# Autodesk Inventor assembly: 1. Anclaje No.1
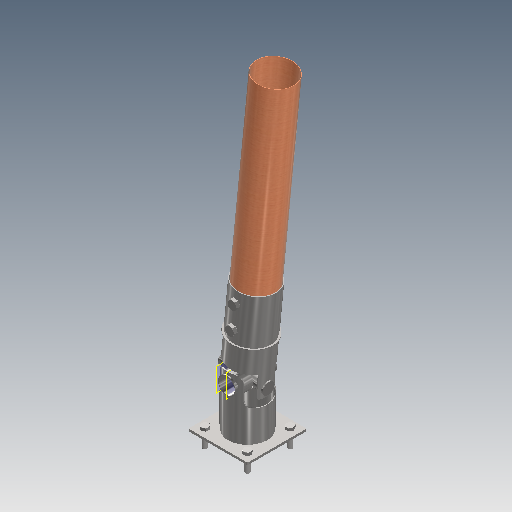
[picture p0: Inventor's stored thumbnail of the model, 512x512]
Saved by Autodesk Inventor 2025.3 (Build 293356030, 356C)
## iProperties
Created: 2025-10
Part Number: 1. Anclaje No.1
Document SubType Name: Assembly
Designer: Asus
Author: Asus
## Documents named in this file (10)
- C:\Users\User\OneDrive - Institucion Universitaria Colegio Mayor de Antioquia\Escritorio\PROTECTO INV\Anclajes Profesor\1. Anclaje de Platinas\1. Anclaje No.1.iam
- C:\Users\User\OneDrive - Institucion Universitaria Colegio Mayor de Antioquia\Escritorio\PROTECTO INV\Anclajes Profesor\1. Anclaje de Platinas\Conector Base (Ensamble).iam
- C:\Users\User\OneDrive - Institucion Universitaria Colegio Mayor de Antioquia\Escritorio\PROTECTO INV\Anclajes Profesor\1. Anclaje de Platinas\Tubo Interior 1.ipt
- C:\Users\User\OneDrive - Institucion Universitaria Colegio Mayor de Antioquia\Escritorio\PROTECTO INV\Anclajes Profesor\1. Anclaje de Platinas\Tubo Exterior 1.ipt
- C:\Users\User\OneDrive - Institucion Universitaria Colegio Mayor de Antioquia\Escritorio\PROTECTO INV\Anclajes Profesor\1. Anclaje de Platinas\Conector a Guadua (Ensamble).iam
- C:\Users\User\OneDrive - Institucion Universitaria Colegio Mayor de Antioquia\Escritorio\PROTECTO INV\Anclajes Profesor\1. Anclaje de Platinas\Pin.ipt
- C:\Users\User\OneDrive - Institucion Universitaria Colegio Mayor de Antioquia\Escritorio\PROTECTO INV\Anclajes Profesor\1. Anclaje de Platinas\Tapa Pin.ipt
- C:\Users\User\OneDrive - Institucion Universitaria Colegio Mayor de Antioquia\Escritorio\PROTECTO INV\Anclajes Profesor\1. Anclaje de Platinas\Guadua.ipt
- C:\Users\User\OneDrive - Institucion Universitaria Colegio Mayor de Antioquia\Documentos\Inventor\Content Center Files\R2025\es-ES\AS 1110\AS 1110 - M24 x 80.ipt
- C:\Users\User\OneDrive - Institucion Universitaria Colegio Mayor de Antioquia\Documentos\Inventor\Content Center Files\R2025\es-ES\AS 1110\AS 1110 - M20 x 70.ipt
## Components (15 placed, 9 different names)
1. Conector Base (Ensamble):1 [sub-assembly] — Nivelación:1, Nivelación:2, Nivelación:3, Coincidencia:1, Nivelación:4, Nivelación:5, Coincidencia:15, Coincidencia:24, Coincidencia:26, Coincidencia:28, Coincidencia:30
2. Tubo Interior 1:1 — Coincidencia:1, Nivelación:4, Coincidencia:16, Coincidencia:17, Nivelación:6
3. Tubo Exterior 1:1 — Nivelación:5, Coincidencia:13, Coincidencia:15
4. Conector a Guadua (Ensamble):1 [sub-assembly]
5. Tapa Pin:1 — Coincidencia:18, Coincidencia:19
6. Guadua:1 — Coincidencia:21, Coincidencia:22
7. Pin:1 — Coincidencia:17, Tangente:1, Coincidencia:18, Coincidencia:19
8. AS 1110 - Métrico M20 x 70:1 — Coincidencia:24
9. AS 1110 - Métrico M20 x 70:2 — Coincidencia:26
10. AS 1110 - Métrico M20 x 70:3 — Coincidencia:28
11. AS 1110 - Métrico M20 x 70:4 — Coincidencia:30
12. AS 1110 - Métrico M24 x 80:1 — Rígido:4
13. AS 1110 - Métrico M24 x 80:2 — Rígido:3
14. AS 1110 - Métrico M24 x 80:3 — Coincidencia:34, Rígido:2
15. AS 1110 - Métrico M24 x 80:4 — Coincidencia:33, Rígido:1
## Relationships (26: Mate 15, Flush 6, WeldJoint 4, Tangent 1)
- Nivelación:1 [Flush]: Conector Base (Ensamble):1
- Nivelación:2 [Flush]: Conector Base (Ensamble):1
- Nivelación:3 [Flush]: Conector Base (Ensamble):1
- Coincidencia:1 [Mate]: Conector Base (Ensamble):1 ↔ Tubo Interior 1:1
- Nivelación:4 [Flush]: Conector Base (Ensamble):1 ↔ Tubo Interior 1:1
- Nivelación:5 [Flush]: Conector Base (Ensamble):1 ↔ Tubo Exterior 1:1
- Coincidencia:13 [Mate]: Tubo Exterior 1:1
- Coincidencia:15 [Mate]: Conector Base (Ensamble):1 ↔ Tubo Exterior 1:1
- Coincidencia:16 [Mate]: Tubo Interior 1:1
- Coincidencia:17 [Mate]: Tubo Interior 1:1 ↔ Pin:1
- Tangente:1: Pin:1
- Coincidencia:18 [Mate]: Tapa Pin:1 ↔ Pin:1
- Coincidencia:19 [Mate]: Tapa Pin:1 ↔ Pin:1
- Nivelación:6 [Flush]: Tubo Interior 1:1
- Coincidencia:21 [Mate]: Guadua:1
- Coincidencia:22 [Mate]: Guadua:1
- Coincidencia:24 [Mate]: Conector Base (Ensamble):1 ↔ AS 1110 - Métrico M20 x 70:1
- Coincidencia:26 [Mate]: Conector Base (Ensamble):1 ↔ AS 1110 - Métrico M20 x 70:2
- Coincidencia:28 [Mate]: Conector Base (Ensamble):1 ↔ AS 1110 - Métrico M20 x 70:3
- Coincidencia:30 [Mate]: Conector Base (Ensamble):1 ↔ AS 1110 - Métrico M20 x 70:4
- Coincidencia:33 [Mate]: AS 1110 - Métrico M24 x 80:4
- Coincidencia:34 [Mate]: AS 1110 - Métrico M24 x 80:3
- Rígido:1 [WeldJoint]: AS 1110 - Métrico M24 x 80:4
- Rígido:2 [WeldJoint]: AS 1110 - Métrico M24 x 80:3
- Rígido:3 [WeldJoint]: AS 1110 - Métrico M24 x 80:2
- Rígido:4 [WeldJoint]: AS 1110 - Métrico M24 x 80:1
